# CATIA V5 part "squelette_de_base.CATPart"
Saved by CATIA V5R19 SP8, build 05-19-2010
Part number: squelette_de_base
Publications: "PointA", "Point2", "Point3", "Pointa", "PointB", "Point_centre_bielle", "Point_origine_aiguille"
Bounding box of the stored display mesh (mm): x -6 to 0, y -28 to 6.5, z -84 to 8
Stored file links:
  C:\Users\ThinkMotion\Desktop\EU_thinkMotion\iao\IAO_MMS_Groupe3\pmayet\pmayet_avant_optimisation\pmayet_avant_optimisation\squelette_de_base.CATPart
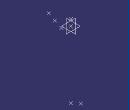
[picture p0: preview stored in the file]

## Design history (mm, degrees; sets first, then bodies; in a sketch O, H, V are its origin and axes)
Set1
  Point1 "PointA": (0, 0, 0)
  Point2 "Point2": (0, -28, 0), relative to Point1
  Point3 "Point3": (0, -12, -8), relative to Point1
  Point4 "Pointa": (0, 0, 8), relative to Point1
  Point5 "PointB": (0, 0, -84), relative to Point1
  Point6 "Point_centre_bielle": type Between, FirstPoint Point2, SecondPoint Point3, Ratio 0.5
  Point7 "Point_origine_aiguille": (-6, 6.5, -84), relative to Point1
Body1 (main body)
